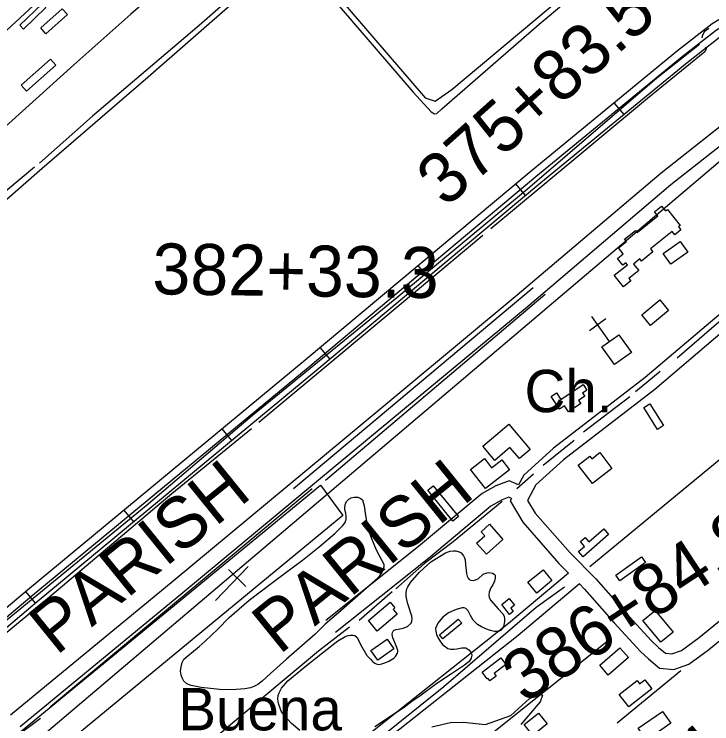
# Model space of a CAD drawing. Extents: x 3392644 to 3430565, y 576657 to 602123.
# Drawn here: x 3410265 to 3411633, y 582765 to 584156 of the extents above; entities that cross this region are included whole.
import ezdxf

# ---------------------------------------------------------------- set-up
doc = ezdxf.new("R2010")
doc.units = 0
for name, color, linetype in [('V-BLDG-OTLN', 7, 'Continuous'), ('V-DTCH-CNTR', 7, 'Continuous'), ('V-ROAD-CNTR', 7, 'Continuous'), ('V-SITE-OTLN', 7, 'Continuous'), ('V-SITE-OTLN-IDEN', 7, 'Continuous'), ('V-SITE-VEGE', 7, 'Continuous'), ('V-SURV-IDEN', 7, 'Continuous'), ('V-TOPO-BNDY', 7, 'Continuous'), ('V-TOPO-GNAM-IDEN', 7, 'Continuous'), ('V-TOPO-SHOR', 7, 'Continuous')]:
    doc.layers.add(name, color=color, linetype=linetype)

msp = doc.modelspace()

# ---------------------------------------------------------------- linework, layer by layer
at = {"layer": 'V-BLDG-OTLN'}
for points in [[(3410276.1, 584133.8), (3410320.1, 584176), (3410327.2, 584168.7), (3410283.1, 584126.4)], [(3410317.1, 584128.8), (3410359, 584166.3), (3410369.3, 584154.8), (3410327.4, 584117.3)], [(3410278.5, 584016.6), (3410336.4, 584067.5), (3410346.9, 584055.5), (3410289, 584004.7)], [(3411555.6, 583729.5), (3411513.2, 583695.5), (3411518, 583689.5), (3411495.6, 583671.6), (3411492.2, 583675.8), (3411479.8, 583665.9), (3411490.2, 583653), (3411470.6, 583637.3), (3411474.3, 583632.6), (3411460.2, 583621.3), (3411442.1, 583643.8), (3411467.9, 583664.5), (3411464.7, 583668.4), (3411458.7, 583663.6), (3411448.2, 583676.6), (3411459.7, 583685.8), (3411450.2, 583697.7), (3411465.9, 583710.3), (3411462.4, 583714.7), (3411483.7, 583731.8), (3411487, 583727.6), (3411527.8, 583760.3), (3411521.3, 583768.5), (3411535, 583779.5), (3411542.7, 583769.9), (3411546.5, 583772.9), (3411571.6, 583741.6), (3411568.1, 583738.8), (3411572.8, 583732.9), (3411560.6, 583723.2)], [(3411538.2, 583686.2), (3411571.5, 583710.1), (3411586.5, 583689.3), (3411553.2, 583665.3)], [(3411496, 583566), (3411531.5, 583595.4), (3411548.7, 583574.6), (3411513.2, 583545.3)], [(3411417.4, 583503.4), (3411450.8, 583527.3), (3411475.6, 583492.6), (3411442.3, 583468.7)], [(3411337.3, 583400.4), (3411381, 583429.6), (3411388.5, 583418.4), (3411380, 583412.8), (3411384.2, 583406.7), (3411372, 583398.5), (3411376.2, 583392.2), (3411352, 583376), (3411344.2, 583387.7), (3411334.6, 583381.3), (3411318.2, 583406), (3411328.8, 583413.1)], [(3411511.6, 583392), (3411538.7, 583349), (3411527, 583341.6), (3411499.8, 583384.6)], [(3411184.3, 583308.5), (3411235.1, 583351.9), (3411277.3, 583302.5), (3411256.1, 583284.4), (3411237.5, 583306.1), (3411207.9, 583280.9)], [(3411399.6, 583235.6), (3411371.6, 583271.8), (3411394, 583289.1), (3411397.9, 583284), (3411413.6, 583296.2), (3411437.6, 583265.1)], [(3411189.4, 583225.6), (3411160.1, 583263.2), (3411187.3, 583284.4), (3411201.3, 583266.5), (3411221.6, 583282.3), (3411236.9, 583262.7)], [(3411086.9, 583231.2), (3411136.3, 583170.6), (3411125.5, 583161.8), (3411076.2, 583222.4)], [(3411191.5, 583097), (3411172.1, 583118.6), (3411188, 583132.8), (3411180.7, 583140.9), (3411197.1, 583155.7), (3411223.8, 583126)], [(3411431, 583135.8), (3411380.9, 583091.7), (3411371.9, 583102), (3411383.8, 583112.4), (3411375.6, 583121.7), (3411384.8, 583129.7), (3411392.3, 583121.1), (3411421.5, 583146.7)], [(3411503.1, 583081), (3411453.1, 583045.1), (3411445.3, 583056), (3411495.3, 583091.9)], [(3411272.5, 583042), (3411302.4, 583066.7), (3411319.9, 583045.4), (3411290, 583020.7)], [(3410959.7, 582967.1), (3411002.2, 583003.1), (3411012, 582991.6), (3411008.3, 582988.5), (3411016.1, 582979.4), (3410977.3, 582946.4)], [(3411221.6, 582998.6), (3411236.2, 583009.9), (3411246.4, 582996.8), (3411238.9, 582991), (3411244, 582984.5), (3411236.8, 582979)], [(3411522.3, 582986.9), (3411557.7, 582944.4), (3411533.6, 582924.4), (3411498.3, 582966.8)], [(3411099.4, 582938.9), (3411136.2, 582969.6), (3411142.8, 582961.6), (3411106, 582930.9)], [(3410964.7, 582908.1), (3410996.6, 582930.7), (3411010, 582911.7), (3410978.1, 582889.1)], [(3411469.8, 582894.3), (3411430.1, 582860.2), (3411413.6, 582879.5), (3411453.3, 582913.5)], [(3411182.7, 582866), (3411219.5, 582894), (3411229.6, 582880.7), (3411206.7, 582863.3), (3411210.7, 582857.9), (3411198.3, 582848.5), (3411194.3, 582853.7), (3411192.9, 582852.6)], [(3411451.9, 582822.1), (3411486.7, 582849.5), (3411491.9, 582842.8), (3411501.8, 582850.7), (3411515.7, 582833.1), (3411470.9, 582797.9)], [(3411265.3, 582763.1), (3411293.8, 582785.7), (3411310.7, 582764.5), (3411282.2, 582741.9)], [(3411488.8, 582755.7), (3411536.7, 582788.9), (3411552.9, 582765.5), (3411505.1, 582732.3)]]:
    msp.add_lwpolyline(points, close=True, dxfattribs=at)
at = {"layer": 'V-DTCH-CNTR'}
for points in [[(3410882.1, 584195.6), (3411047.4, 584003), (3411083.1, 583964.4), (3411089.2, 583960.1), (3411094, 583960.7), (3411103.8, 583970.1), (3411294.5, 584136.2), (3411604.7, 584395.4)], [(3409182.8, 582089.4), (3409092.7, 582198.3), (3408907.2, 582416.2), (3408813.8, 582525.5), (3408808.5, 582534.5), (3408807.9, 582537.3), (3408807.3, 582543.5), (3408808.1, 582544.9), (3408809.5, 582548.3), (3409025.3, 582733.7), (3409286, 582959.6), (3409402.1, 583061.5), (3409500.5, 583147.9), (3409737.2, 583347.4), (3409967.1, 583549.1), (3410164.7, 583718.4), (3410319.6, 583853.5), (3410527.7, 584033), (3410699.4, 584182.2), (3410804.5, 584272.9)], [(3409200.4, 582089.5), (3409528.3, 582368.3), (3409839.9, 582625.7), (3410145.1, 582881.8), (3410166.9, 582900.2), (3410524, 583192.8), (3410732.7, 583369.5), (3411015.5, 583600.4), (3411271.8, 583813.3), (3411525.5, 584031), (3411609.4, 584096.7)]]:
    msp.add_lwpolyline(points, dxfattribs=at)
at = {"layer": 'V-ROAD-CNTR'}
for p, q in [((3411461.2, 583958.9), (3411442.1, 583982.1)), ((3411268.2, 583800.1), (3411249, 583823.1)), ((3411076.5, 583639.7), (3411057.2, 583662.7)), ((3410884.8, 583479.2), (3410865.5, 583502.2)), ((3410692.2, 583319.7), (3410673.1, 583342.8)), ((3410499.6, 583160.3), (3410480.5, 583183.4)), ((3410307.1, 583001), (3410287.8, 583023.9))]:
    msp.add_line(p, q, dxfattribs=at)
for points in [[(3410997.4, 584802.8), (3410706.7, 584547.3), (3410393.1, 584257.2), (3410035, 583925), (3409724.5, 583647.1)], [(3411692.4, 584155.2), (3411661.6, 584153.2), (3411633.9, 584136.8), (3411566, 584083.7), (3411278.8, 583848.1), (3410835.7, 583477.3), (3410290.9, 583026.6), (3409909.9, 582706)], [(3411693.4, 584140.2), (3411666.2, 584138.5), (3411642.4, 584124.3), (3411575.4, 584072), (3411288.3, 583836.5), (3410845.3, 583465.8), (3410300.5, 583015.1), (3409814.8, 582606.3), (3409387.6, 582252.8), (3409195.3, 582092.6)], [(3411694.3, 584125.3), (3411670.8, 584123.7), (3411650.9, 584111.9), (3411584.8, 584060.3), (3411297.9, 583825), (3410854.9, 583454.2), (3410310.1, 583003.5), (3410171.2, 582886.6)], [(3411717.9, 583988.8), (3411534, 583844), (3411251.7, 583604.5), (3410912.2, 583322.5), (3410576.7, 583044.4), (3410257.7, 582781.8)], [(3411723.4, 583955), (3411553, 583820.8), (3411271, 583581.5), (3410931.3, 583299.4), (3410595.8, 583021.3), (3410276.6, 582758.6)], [(3411775.8, 583642.6), (3411743.8, 583637.3), (3411710.4, 583618.3), (3411639.1, 583559), (3411502.6, 583443.1), (3411323.1, 583304.8), (3411264.5, 583252), (3411254.4, 583233)], [(3411780.7, 583613), (3411754, 583608.6), (3411727.6, 583593.6), (3411658.4, 583536), (3411521.5, 583419.7), (3411342.4, 583281.8), (3411288.5, 583233.2), (3411272.2, 583202.5), (3411287.2, 583177.5), (3411355.3, 583099.5), (3411405.8, 583049), (3411464.3, 582982.9), (3411515.1, 582927.2), (3411529, 582914.3), (3411542.7, 582902.9), (3411554.9, 582901.7), (3411574.1, 582908.5), (3411608.4, 582933.5), (3411694.9, 583004.1), (3411750.2, 583041.1), (3411800.1, 583069.9), (3411829.9, 583088.3), (3411847.6, 583090.9), (3411873.4, 583093.6)], [(3411254.4, 583233), (3411236.2, 583241), (3411209.6, 583231.2), (3411182.9, 583215.8), (3411058.4, 583112.1), (3410876.6, 582967)], [(3411240.4, 583206.4), (3411235.2, 583208.7), (3411222.4, 583203.9), (3411200.1, 583191.1), (3411077.4, 583088.8), (3410895.3, 582943.6)], [(3411240.4, 583206.4), (3411237.8, 583201.6), (3411262.8, 583159.8), (3411333.3, 583079), (3411352.3, 583060)], [(3411352.3, 583060), (3411234.7, 582961.1), (3410970.9, 582752.3), (3410878.5, 582672.9)], [(3411373.6, 583038.8), (3411384, 583028.4), (3411441.9, 582962.8), (3411493.8, 582906), (3411509.1, 582891.8), (3411530.6, 582873.9), (3411558.7, 582871.2), (3411588.3, 582881.7), (3411626.7, 582909.8), (3411712.8, 582979.9), (3411766.1, 583015.6), (3411815.4, 583044.2), (3411840.4, 583059.5), (3411851.3, 583061.2), (3411876.5, 583063.8)], [(3411373.6, 583038.8), (3411253.7, 582937.9), (3410990, 582729.2), (3410898.1, 582650.2)]]:
    msp.add_lwpolyline(points, dxfattribs=at)
at = {"layer": 'V-SITE-OTLN'}
for p, q in [((3411432.7, 583514.1), (3411397.9, 583562.9)), ((3411425.8, 583558.3), (3411393.2, 583535)), ((3410659.7, 583006.2), (3410723.8, 583072.8)), ((3410719.6, 583034), (3410685.2, 583067.2))]:
    msp.add_line(p, q, dxfattribs=at)
msp.add_lwpolyline([(3410910, 583172.6), (3410326.2, 582692.2), (3410278.8, 582750), (3410866.1, 583232.3)], close=True, dxfattribs=at)
at = {"layer": 'V-SITE-VEGE'}
msp.add_lwpolyline([(3410989.9, 583077), (3410989.8, 583072.5), (3410988.6, 583067.9), (3410986.1, 583060.9), (3410977.5, 583049.3), (3410901, 582982.4), (3410875.1, 582960.1), (3410855, 582939.3), (3410799.3, 582891.5), (3410767.6, 582862.9), (3410751.5, 582848.3), (3410742.8, 582841.8), (3410735.4, 582837.6), (3410728.3, 582835.3), (3410717.7, 582833.1), (3410700.6, 582831.5), (3410674.3, 582831.3), (3410631.6, 582835.5), (3410612.1, 582839.5), (3410603.6, 582842.9), (3410597.5, 582848.2), (3410594.2, 582854.8), (3410592.3, 582860.1), (3410591.4, 582867.6), (3410592.3, 582876.3), (3410594.8, 582884.8), (3410598.1, 582891.2), (3410605.4, 582898), (3410628.1, 582915.9), (3410639.7, 582926.5), (3410664.3, 582950.2), (3410686.7, 582973.1), (3410726.2, 583006.6), (3410769.4, 583039.5), (3410795.2, 583059.4), (3410830.7, 583085.3), (3410863.3, 583111.3), (3410894.2, 583137.3), (3410904.5, 583148), (3410909.5, 583153.4), (3410914, 583159.4), (3410915.8, 583163.8), (3410916, 583164.4), (3410916.3, 583170.6), (3410915.3, 583177.3), (3410913.6, 583184.1), (3410913.3, 583189.3), (3410914.9, 583196.4), (3410917.6, 583200.9), (3410921.6, 583204.8), (3410926.1, 583207.4), (3410932, 583208.7), (3410938.8, 583208.6), (3410943.9, 583206.9), (3410948, 583203.3), (3410950.5, 583196.6), (3410951.3, 583192.1), (3410954.2, 583172.7), (3410957.4, 583154), (3410960.7, 583142.1), (3410966.1, 583127.6), (3410975.2, 583105.4), (3410980, 583095.6), (3410986.2, 583084.5), (3410989.5, 583079)], close=True, dxfattribs=at)
for points in [[(3410972.2, 582883.6), (3410975.2, 582882.1), (3410980.1, 582881.1), (3410985.9, 582882.3), (3410991.9, 582884), (3410999.9, 582887.4), (3411009.8, 582893.2), (3411013, 582896.6), (3411016.7, 582903.1), (3411017.6, 582905.5), (3411017.7, 582908.5), (3411015.8, 582914.1), (3411012.7, 582920.4), (3411007.7, 582933.2), (3411006.3, 582939.3), (3411007.2, 582943.7), (3411008.4, 582946.1), (3411010.6, 582948.1), (3411014.1, 582949.1), (3411021.5, 582950.4), (3411028, 582951.9), (3411036.8, 582955.5), (3411044, 582961.7), (3411045.2, 582965.6), (3411045.8, 582970.7), (3411045.2, 582975.7), (3411037.3, 582999.9), (3411034.5, 583010.6), (3411033.8, 583015.5), (3411033.6, 583021.7), (3411035.4, 583029.2), (3411037, 583033), (3411042.4, 583041.4), (3411059.8, 583062.1), (3411082.6, 583082.3), (3411110.8, 583099.9), (3411116, 583101.8), (3411120.5, 583103.1), (3411126.9, 583103.9), (3411131.3, 583103.5), (3411137.6, 583101.5), (3411141.5, 583099.6), (3411146.4, 583093.8), (3411148.4, 583089.8), (3411149.4, 583086.1), (3411150.5, 583076.1), (3411151.6, 583065), (3411152.2, 583059.2), (3411153.7, 583053.9), (3411155.4, 583050.1), (3411157.4, 583047.4), (3411160.5, 583045.8), (3411166, 583045.3), (3411170.2, 583046.6), (3411175.3, 583049), (3411185.2, 583057.6), (3411192.5, 583060.2), (3411196.1, 583061)], [(3411196.1, 583061), (3411203.1, 583059.8), (3411206.3, 583058.2), (3411208.2, 583055.6), (3411208.7, 583050.3), (3411206.9, 583043.9), (3411203.7, 583037.1), (3411200.2, 583030.8), (3411196.5, 583022.3), (3411196.1, 583015.8), (3411196.9, 583012.4), (3411199.9, 583006), (3411214.3, 582989.7), (3411223.3, 582980.2), (3411226.3, 582975.3), (3411227, 582970.3), (3411226.9, 582965.8), (3411226.4, 582961), (3411224.6, 582955.4), (3411221.4, 582949.4), (3411220.2, 582947.8), (3411216.6, 582946.4), (3411213.3, 582945.7), (3411207.1, 582945.4), (3411199.2, 582947.5), (3411191.8, 582950.1), (3411181.6, 582954.8), (3411174.1, 582959.5), (3411165.3, 582967.8), (3411159.9, 582976.9), (3411155.7, 582985.8), (3411153.2, 582988.9), (3411151.1, 582990.9), (3411147.8, 582991.7), (3411143.8, 582991.6), (3411131.8, 582988.7), (3411117, 582982.1), (3411105, 582972.7), (3411096, 582962), (3411091.6, 582951.4), (3411092.1, 582945.9), (3411093.6, 582939.9), (3411096, 582933.6), (3411101.1, 582925), (3411105.9, 582919.2), (3411115.7, 582912.2), (3411121.1, 582910.7), (3411127.5, 582910.7), (3411133.3, 582911.7), (3411143.4, 582913.6), (3411151.2, 582913.3), (3411156.7, 582909.3), (3411161.2, 582904.5), (3411162.6, 582899.1), (3411161.6, 582893.4), (3411157.6, 582887), (3411148.2, 582879.5), (3411122.7, 582862.3), (3411093.9, 582843.6), (3411060.4, 582818.9), (3411045.2, 582808.5), (3411029.8, 582796.8), (3411013.3, 582785.7), (3410972.6, 582758.9)], [(3410825.4, 582751.5), (3410809.3, 582765.2), (3410795.9, 582779.2), (3410789, 582789.3), (3410786.8, 582794.9), (3410784.2, 582802.4), (3410782.9, 582808.2), (3410782.4, 582813.4), (3410782.9, 582820), (3410784.5, 582825.1), (3410789.1, 582834.7), (3410801.6, 582848.8), (3410838.1, 582878.6), (3410872.8, 582906.5), (3410899.8, 582926.9), (3410912, 582934.5), (3410914.5, 582935.6), (3410920.4, 582937.7), (3410924.9, 582938.4), (3410930.1, 582938.3), (3410932.9, 582937.4), (3410937.1, 582934.7), (3410940.6, 582928.6), (3410944.1, 582920), (3410956.7, 582898.7), (3410963.7, 582891), (3410968.8, 582886.2), (3410972.2, 582883.6)], [(3411084.1, 582758.4), (3411121.1, 582767.2), (3411145.8, 582768), (3411189.4, 582763), (3411239, 582781.1), (3411275.1, 582813.2), (3411295.9, 582823.7), (3411301.3, 582820.9), (3411296.9, 582807.3), (3411259.1, 582763)]]:
    msp.add_lwpolyline(points, dxfattribs=at)
at = {"layer": 'V-TOPO-BNDY'}
msp.add_lwpolyline([(3412089.5, 584240.4), (3409553.2, 582090.8)], dxfattribs=at)
at = {"layer": 'V-TOPO-SHOR'}
for p, q in [((3410813.2, 583225.5), (3411283.3, 583619.7)), ((3410875.8, 583242.3), (3411306.4, 583606.6)), ((3411661.5, 583564.3), (3411565.5, 583481.6)), ((3411532, 583455.5), (3411483.6, 583415.2)), ((3411472.4, 583405.8), (3411381.5, 583336.1)), ((3411363.3, 583319.9), (3411302.4, 583270.9)), ((3411283.5, 583254.1), (3411251.2, 583225.2)), ((3410336.5, 582798.4), (3410849.4, 583225.7)), ((3411006.2, 583023.1), (3410941.7, 582967.3)), ((3411167.9, 582719), (3411434.2, 582931)), ((3411448, 582766.2), (3411572.9, 582868.9)), ((3410267.5, 582738.8), (3410316.8, 582775.3))]:
    msp.add_line(p, q, dxfattribs=at)
for points in [[(3410902, 584188.8), (3411070.9, 583991.5), (3411090.7, 583985), (3411123.6, 584008.2), (3411610.2, 584415.6)], [(3410706.3, 584341), (3410622.5, 584267.3), (3410494, 584155.5), (3410382.3, 584056.4), (3410233.5, 583923), (3410163.1, 583865.5), (3410105.9, 583822.1), (3410022.2, 583749.8), (3409920.8, 583657.3), (3409761, 583518.7)], [(3410789.9, 584275.6), (3410627.9, 584133.6), (3410418.5, 583955.6), (3410314.5, 583863.8)], [(3411627.9, 584127.5), (3411618.2, 584120.8), (3411614.6, 584112.7), (3411613.9, 584109.3)], [(3411620.3, 584091.3), (3411622.3, 584087.9), (3411619.5, 584081.8)], [(3411619.5, 584081.8), (3411507.2, 583990.2), (3411300.9, 583818.4), (3411199.8, 583734.8)], [(3410304.7, 583855.8), (3410199.4, 583768.2), (3410103.7, 583681.7), (3410002.5, 583598.1), (3409878.2, 583486.2), (3409784.7, 583407.2), (3409666.6, 583301.3), (3409561.2, 583208.2), (3409497.7, 583154.6), (3409443.9, 583109.2), (3409323.9, 583007.5), (3409186.4, 582887.6), (3409055.1, 582773.8)], [(3411184.4, 583722.1), (3411019.9, 583584.4), (3410823.3, 583420.6), (3410745.2, 583355)], [(3411394.1, 583072.7), (3411667, 583297.9), (3411778.8, 583390.6)], [(3410730.5, 583343), (3410574.4, 583215.4), (3410317.8, 582999.3), (3410164.4, 582873)], [(3411222.5, 583200.3), (3411125.9, 583121.1), (3411069.9, 583078.9), (3411013.9, 583029.2)], [(3410411, 582274.3), (3410703.6, 582526), (3410789.1, 582582.4), (3411108.1, 582837.5), (3411288.9, 582993.1), (3411344.8, 583032.9)], [(3410922.8, 582954), (3410862, 582907), (3410747.1, 582811), (3410643.5, 582723.7), (3410629.4, 582710.9), (3410616, 582694.7), (3410597, 582673.7), (3410452.1, 582553.5), (3410296.6, 582423.9)]]:
    msp.add_lwpolyline(points, dxfattribs=at)

# ---------------------------------------------------------------- texts
at = {"layer": 'V-SITE-OTLN-IDEN'}
for s, p in [('Ch.', (3411266, 583375.4)), ('Buena', (3410586.8, 582751.7))]:
    msp.add_text(s, height=83, dxfattribs=at).set_placement(p)
at = {"layer": 'V-SURV-IDEN'}
for s, rotation, p in [('375+83.5', 41.8099, (3411111.6, 583774.5)), ('382+33.3', 359.1981, (3410535.7, 583606.7)), ('386+84.8', 33.3237, (3411266.7, 582802.4)), ('390+14.4', 39.3224, (3411390.6, 582464.5))]:
    msp.add_text(s, height=100, rotation=rotation, dxfattribs=at).set_placement(p)
at = {"layer": 'V-TOPO-GNAM-IDEN'}
for p in [(3410347.5, 582896.9), (3410785.1, 582898.5)]:
    msp.add_text('PARISH', height=100, rotation=39.0222, dxfattribs=at).set_placement(p)

doc.saveas('drawing.dxf')
